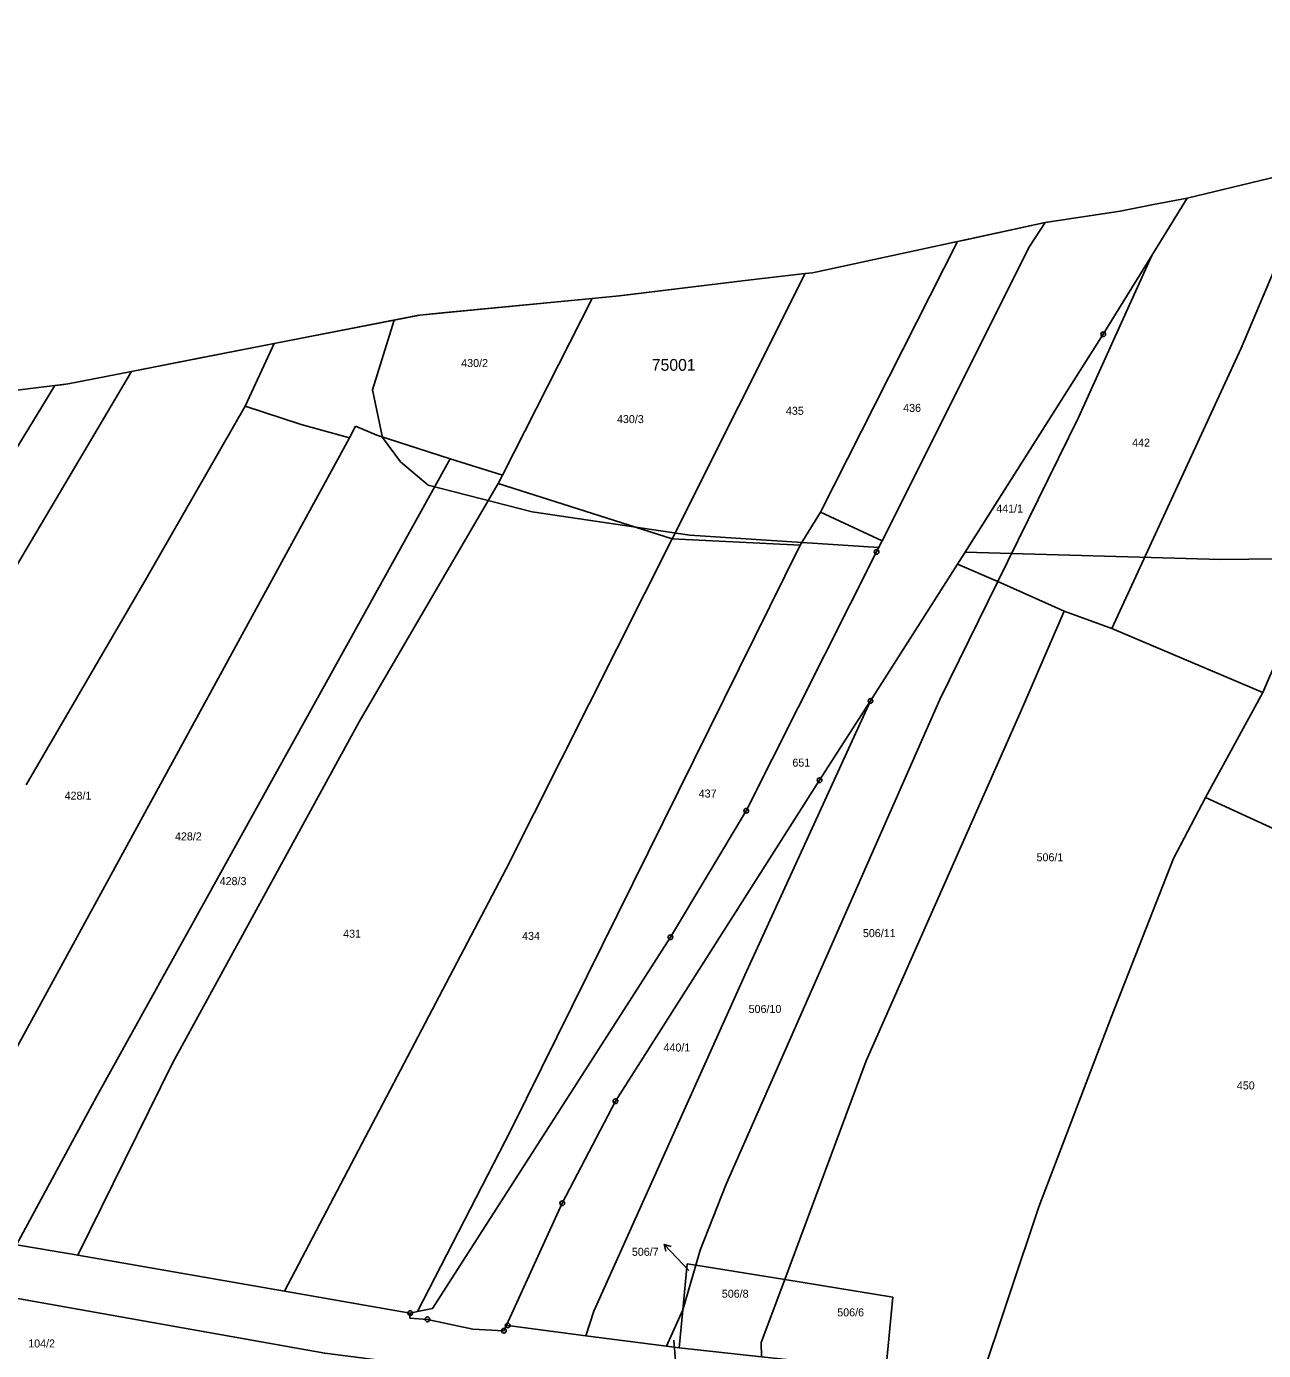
# Model space of a CAD drawing. Extents: x -743888 to -742027, y -1128394 to -1126768.
# Drawn here: x -743261.6 to -742998.7, y -1127100.1 to -1126818.8 of the extents above; entities that cross this region are included whole.
import ezdxf

# ---------------------------------------------------------------- set-up
doc = ezdxf.new("R2010")
doc.units = 0
for name, color, linetype in [('Vrstva 1', 7, 'Continuous'), ('Vrstva 13', 7, 'Continuous'), ('Vrstva 16', 7, 'Continuous'), ('Vrstva 18', 7, 'Continuous'), ('Vrstva 24', 7, 'Continuous'), ('Vrstva 52', 7, 'Continuous'), ('Vrstva 53', 7, 'Continuous'), ('Vrstva 6', 7, 'Continuous')]:
    doc.layers.add(name, color=color, linetype=linetype)

msp = doc.modelspace()

# ---------------------------------------------------------------- linework, layer by layer
at = {"layer": 'Vrstva 1'}
for points in [[(-743022.51, -1126867.46), (-743014.97, -1126855.23)], [(-743032.8, -1126884.17), (-743022.51, -1126867.46)], [(-743063.8, -1126932.98), (-743032.8, -1126884.17)], [(-743108.67, -1126985.4), (-743080.97, -1126930.41)], [(-743082.27, -1126962.07), (-743063.8, -1126932.98)], [(-743093.1, -1126978.92), (-743082.27, -1126962.07)], [(-743136.47, -1127047.12), (-743093.1, -1126978.92)], [(-743124.8, -1127012.28), (-743108.67, -1126985.4)], [(-743175.35, -1127091.16), (-743124.8, -1127012.28)], [(-743147.78, -1127068.8), (-743136.47, -1127047.12)], [(-743159.64, -1127094.74), (-743147.78, -1127068.8)], [(-743263.8, -1127077.63), (-743251.53, -1127079.71)], [(-743251.53, -1127079.71), (-743250.75, -1127079.85)], [(-743250.75, -1127079.85), (-743206.78, -1127087.5)], [(-743122.16, -1127091.42), (-743121.21, -1127081.67)], [(-743121.21, -1127081.67), (-743119.42, -1127081.96)], [(-743119.42, -1127081.96), (-743100.51, -1127085.04)], [(-743287.04, -1127084.88), (-743198.26, -1127100.66)], [(-743100.51, -1127085.04), (-743077.54, -1127088.79)], [(-743206.78, -1127087.5), (-743180.08, -1127092.14)], [(-743079.01, -1127104.25), (-743077.54, -1127088.79)], [(-743180.08, -1127092.14), (-743178.51, -1127091.81)], [(-743178.51, -1127091.81), (-743175.35, -1127091.16)], [(-743122.95, -1127099.53), (-743122.16, -1127091.42)], [(-743180.17, -1127093.19), (-743180.08, -1127092.14)], [(-743180.17, -1127093.19), (-743176.42, -1127093.47)], [(-743176.42, -1127093.47), (-743166.78, -1127095.57)], [(-743160.17, -1127095.91), (-743159.64, -1127094.74)], [(-743159.64, -1127094.74), (-743159.38, -1127094.77)], [(-743159.38, -1127094.77), (-743142.75, -1127096.94)], [(-743166.78, -1127095.57), (-743160.17, -1127095.91)], [(-743142.75, -1127096.94), (-743125.61, -1127099.18)], [(-743125.61, -1127099.18), (-743122.95, -1127099.53)], [(-743122.95, -1127099.53), (-743105.44, -1127101.41)]]:
    msp.add_lwpolyline(points, dxfattribs=at)
at = {"layer": 'Vrstva 13'}
for points in [[(-743014.97, -1126855.23), (-742997.62, -1126851.06)], [(-743022.12, -1126856.61), (-743014.97, -1126855.23)], [(-743045.12, -1126860.39), (-743029.24, -1126857.99)], [(-743029.24, -1126857.99), (-743022.12, -1126856.61)], [(-743063.79, -1126864.46), (-743045.12, -1126860.39)], [(-743081.5, -1126868.29), (-743066.4, -1126865.02)], [(-743066.4, -1126865.02), (-743063.79, -1126864.46)], [(-743094.61, -1126871.12), (-743081.5, -1126868.29)], [(-743108.94, -1126872.71), (-743096.16, -1126871.29)], [(-743096.16, -1126871.29), (-743094.61, -1126871.12)], [(-743135.6, -1126876), (-743108.94, -1126872.71)], [(-743166.37, -1126878.96), (-743141.43, -1126876.56)], [(-743141.43, -1126876.56), (-743135.6, -1126876)], [(-743209.04, -1126886.14), (-743178.59, -1126880.18)], [(-743178.59, -1126880.18), (-743178.08, -1126880.08)], [(-743178.08, -1126880.08), (-743166.37, -1126878.96)], [(-743225.02, -1126889.27), (-743209.04, -1126886.14)], [(-743239.29, -1126892.07), (-743225.02, -1126889.27)], [(-743252.8, -1126894.71), (-743239.29, -1126892.07)], [(-743271.77, -1126897.03), (-743255.64, -1126895.06)], [(-743255.64, -1126895.06), (-743254.17, -1126894.88)], [(-743254.17, -1126894.88), (-743252.8, -1126894.71)]]:
    msp.add_lwpolyline(points, dxfattribs=at)
at = {"layer": 'Vrstva 16'}
msp.add_line((-743125.75, -1127079), (-743126.1, -1127077.54), dxfattribs=at)
for points in [[(-743123.35, -1127080.45), (-743126.1, -1127077.54), (-743124.66, -1127077.97)], [(-743120.87, -1127083.07), (-743123.35, -1127080.45)], [(-743124.1, -1127097.89), (-743123.74, -1127102.32)]]:
    msp.add_lwpolyline(points, dxfattribs=at)
at = {"layer": 'Vrstva 24'}
for p, q in [((-743032.85, -1126884.17), (-743032.75, -1126884.17)), ((-743081.02, -1126930.41), (-743080.92, -1126930.41)), ((-743082.32, -1126962.07), (-743082.22, -1126962.07)), ((-743093.15, -1126978.92), (-743093.05, -1126978.92)), ((-743108.72, -1126985.4), (-743108.62, -1126985.4)), ((-743124.85, -1127012.28), (-743124.75, -1127012.28)), ((-743136.52, -1127047.12), (-743136.42, -1127047.12)), ((-743147.83, -1127068.8), (-743147.73, -1127068.8)), ((-743180.13, -1127092.14), (-743180.03, -1127092.14)), ((-743176.47, -1127093.47), (-743176.37, -1127093.47)), ((-743159.43, -1127094.77), (-743159.33, -1127094.77)), ((-743160.22, -1127095.91), (-743160.12, -1127095.91))]:
    msp.add_line(p, q, dxfattribs=at)
for centre in [(-743032.8, -1126884.17), (-743080.97, -1126930.41), (-743082.27, -1126962.07), (-743093.1, -1126978.92), (-743108.67, -1126985.4), (-743124.8, -1127012.28), (-743136.47, -1127047.12), (-743147.78, -1127068.8), (-743180.08, -1127092.14), (-743176.42, -1127093.47), (-743159.38, -1127094.77), (-743160.17, -1127095.91)]:
    msp.add_circle(centre, 0.499, dxfattribs=at)
at = {"layer": 'Vrstva 52'}
for points in [[(-743014.97, -1126855.23), (-742997.62, -1126851.06), (-742987.15, -1126848.45), (-742983.82, -1126847.62), (-742967.54, -1126845.19), (-742949.34, -1126840.52), (-742925.21, -1126834.34), (-742909.52, -1126830.92), (-742885.68, -1126828.21), (-742883.83, -1126827.8), (-742866.72, -1126824.05), (-742849.79, -1126820.34), (-742842.63, -1126818.77)], [(-743062.18, -1126930.43), (-743032.8, -1126884.17), (-743022.51, -1126867.46), (-743014.97, -1126855.23)], [(-743183.51, -1126881.14), (-743178.08, -1126880.08), (-743173.31, -1126879.62), (-743141.43, -1126876.56), (-743135.66, -1126876.01), (-743108.94, -1126872.71), (-743096.16, -1126871.29), (-743094.61, -1126871.12), (-743063.79, -1126864.46), (-743061.99, -1126864.07), (-743045.12, -1126860.39)], [(-743080.5, -1126929.47), (-743079.79, -1126928.05), (-743048.51, -1126865.51), (-743045.12, -1126860.39)], [(-743402.66, -1126899.83), (-743385.6, -1126903.46), (-743372.24, -1126906.89), (-743371.28, -1126907.14), (-743345.39, -1126906.84), (-743334.69, -1126906.72), (-743314.63, -1126903.54), (-743292.9, -1126900.09), (-743279.71, -1126898), (-743271.77, -1126897.03), (-743255.64, -1126895.06), (-743252.8, -1126894.71), (-743239.29, -1126892.07), (-743209.04, -1126886.14), (-743183.51, -1126881.14)], [(-743080.5, -1126929.47), (-743120.69, -1126926.88), (-743154.19, -1126921.88), (-743176.25, -1126916.25), (-743182.19, -1126911.25), (-743186, -1126906.13), (-743188.13, -1126896), (-743183.51, -1126881.14)], [(-743080.5, -1126929.47), (-743080.97, -1126930.41), (-743108.67, -1126985.4), (-743124.8, -1127012.28), (-743175.35, -1127091.16), (-743178.51, -1127091.81), (-743180.08, -1127092.14), (-743206.78, -1127087.5), (-743250.75, -1127079.85), (-743251.53, -1127079.71), (-743263.8, -1127077.63)], [(-742996.77, -1127117.36), (-743017.52, -1127113.57), (-743059.24, -1127107.7), (-743079.38, -1127104.87), (-743079.01, -1127104.25), (-743105.44, -1127101.41), (-743122.95, -1127099.53), (-743125.61, -1127099.18), (-743142.75, -1127096.94), (-743159.38, -1127094.77), (-743159.64, -1127094.74), (-743147.78, -1127068.8), (-743136.47, -1127047.12), (-743093.1, -1126978.92), (-743082.27, -1126962.07), (-743063.8, -1126932.98), (-743062.18, -1126930.43)], [(-743062.18, -1126930.43), (-743007.81, -1126932), (-742972.19, -1126931.63), (-742966.69, -1126932), (-742958.19, -1126931.63), (-742925.13, -1126931.13), (-742911.13, -1126930.25), (-742889.44, -1126930.75), (-742864, -1126931.13), (-742834.31, -1126932.38), (-742823.69, -1126934.13), (-742801.63, -1126940.13), (-742784.25, -1126946.38), (-742764.75, -1126955.38), (-742762.63, -1126960), (-742759.63, -1126959.63), (-742751.19, -1126966.75), (-742748.56, -1126970.88), (-742745.84, -1126975.32)], [(-743287.04, -1127084.88), (-743198.26, -1127100.66), (-743183.34, -1127102.57), (-743205.03, -1127140.21), (-743235.54, -1127186.77), (-743246.95, -1127204.21), (-743264.54, -1127233.06)]]:
    msp.add_lwpolyline(points, dxfattribs=at)
at = {"layer": 'Vrstva 6'}
for points in [[(-743003.48, -1126887.11), (-742987.15, -1126848.45)], [(-743048.51, -1126865.51), (-743045.12, -1126860.39)], [(-743092.91, -1126921.98), (-743063.79, -1126864.46)], [(-743079.79, -1126928.05), (-743048.51, -1126865.51)], [(-743038.05, -1126901.87), (-743022.51, -1126867.46)], [(-743124.42, -1126927.65), (-743096.16, -1126871.29)], [(-743160.51, -1126914.13), (-743141.43, -1126876.56)], [(-743215.19, -1126899.42), (-743209.04, -1126886.14)], [(-743030.98, -1126946.66), (-743003.48, -1126887.11)], [(-743275.93, -1126953.86), (-743239.29, -1126892.07)], [(-743292.37, -1126955.23), (-743255.64, -1126895.06)], [(-743236.45, -1126936.5), (-743215.19, -1126899.42)], [(-743215.19, -1126899.42), (-743203.25, -1126903.35)], [(-743203.25, -1126903.35), (-743193, -1126906.14)], [(-743055.18, -1126936.67), (-743038.05, -1126901.87)], [(-742998.88, -1126960.31), (-742973.7, -1126901.64)], [(-743266.09, -1127040.1), (-743193, -1126906.14)], [(-743193, -1126906.14), (-743191.74, -1126903.68)], [(-743191.74, -1126903.68), (-743187.18, -1126905.63)], [(-743187.18, -1126905.63), (-743171.59, -1126910.6)], [(-743246.71, -1127046.03), (-743171.59, -1126910.6)], [(-743171.59, -1126910.6), (-743160.51, -1126914.13)], [(-743161.41, -1126915.91), (-743160.51, -1126914.13)], [(-743190.96, -1126966.49), (-743161.41, -1126915.91)], [(-743161.41, -1126915.91), (-743124.42, -1126927.65)], [(-743097.21, -1126928.95), (-743092.91, -1126921.98)], [(-743092.91, -1126921.98), (-743079.79, -1126928.05)], [(-743159.7, -1126997.73), (-743124.42, -1126927.65)], [(-743124.42, -1126927.65), (-743097.21, -1126928.95)], [(-743080.97, -1126930.41), (-743079.79, -1126928.05)], [(-743158.66, -1127053.1), (-743097.21, -1126928.95)], [(-743063.8, -1126932.98), (-743055.18, -1126936.67)], [(-743261.68, -1126979.9), (-743236.45, -1126936.5)], [(-743067.57, -1126961.77), (-743055.18, -1126936.67)], [(-743055.18, -1126936.67), (-743041.11, -1126943.01)], [(-743050.16, -1126963.96), (-743041.11, -1126943.01)], [(-743041.11, -1126943.01), (-743030.98, -1126946.66)], [(-743030.98, -1126946.66), (-742998.88, -1126960.31)], [(-743112.93, -1127064.74), (-743067.57, -1126961.77)], [(-743109, -1127020.35), (-743082.27, -1126962.07)], [(-743011.05, -1126982.56), (-742998.88, -1126960.31)], [(-743083.16, -1127038.56), (-743050.16, -1126963.96)], [(-743230.59, -1127039.01), (-743190.96, -1126966.49)], [(-743017.87, -1126995.55), (-743011.05, -1126982.56)], [(-743011.05, -1126982.56), (-742982.82, -1126995.58)], [(-743031.05, -1127029.12), (-743017.87, -1126995.55)], [(-743206.78, -1127087.5), (-743159.7, -1126997.73)], [(-743141.05, -1127091.73), (-743109, -1127020.35)], [(-743046.52, -1127069.6), (-743031.05, -1127029.12)], [(-743100.51, -1127085.04), (-743083.16, -1127038.56)], [(-743250.75, -1127079.85), (-743230.59, -1127039.01)], [(-743263.8, -1127077.63), (-743246.71, -1127046.03)], [(-743178.51, -1127091.81), (-743158.66, -1127053.1)], [(-743118.49, -1127078.74), (-743112.93, -1127064.74)], [(-743059.24, -1127107.7), (-743046.52, -1127069.6)], [(-743119.42, -1127081.96), (-743118.49, -1127078.74)], [(-743122.16, -1127091.42), (-743119.42, -1127081.96)], [(-743105.49, -1127098.37), (-743100.51, -1127085.04)], [(-743142.75, -1127096.94), (-743141.05, -1127091.73)], [(-743125.61, -1127099.18), (-743122.16, -1127091.42)], [(-743105.49, -1127098.37), (-743105.44, -1127101.41)]]:
    msp.add_lwpolyline(points, dxfattribs=at)

# ---------------------------------------------------------------- texts
at = {"layer": 'Vrstva 16'}
msp.add_text('506/7', height=1.7, dxfattribs=at).set_placement((-743132.99, -1127079.97))
at = {"layer": 'Vrstva 18'}
for s, height, p in [('430/2', 1.7, (-743169.25, -1126891.13)), ('435', 1.7, (-743100.25, -1126901.28)), ('436', 1.7, (-743075.33, -1126900.66)), ('430/3', 1.7, (-743136.15, -1126903.04)), ('442', 1.7, (-743026.66, -1126908.04)), ('441/1', 1.7, (-743055.54, -1126922.04)), ('651', 1.7, (-743098.87, -1126976.03)), ('428/1', 1.7, (-743253.54, -1126983.05)), ('437', 1.7, (-743118.77, -1126982.6)), ('428/2', 1.7, (-743230.08, -1126991.71)), ('506/1', 1.7, (-743046.98, -1126996.14)), ('428/3', 1.7, (-743220.59, -1127001.21)), ('431', 1.7, (-743194.34, -1127012.38)), ('434', 1.7, (-743156.31, -1127012.85)), ('506/11', 1.7, (-743083.89, -1127012.26)), ('506/10', 1.7, (-743108.17, -1127028.37)), ('440/1', 1.7, (-743126.26, -1127036.56)), ('450', 1.7, (-743004.41, -1127044.63)), ('506/7', 0.1, (-743120.87, -1127083.07)), ('506/8', 1.7, (-743113.87, -1127088.87)), ('506/6', 1.7, (-743089.34, -1127092.84)), ('104/2', 1.7, (-743261.27, -1127099.45)), ('506/9', 0.1, (-743124.1, -1127097.89))]:
    msp.add_text(s, height=height, dxfattribs=at).set_placement(p)
at = {"layer": 'Vrstva 53'}
msp.add_text('75001', height=2.5, dxfattribs=at).set_placement((-743128.74, -1126891.92))

doc.saveas('drawing.dxf')
